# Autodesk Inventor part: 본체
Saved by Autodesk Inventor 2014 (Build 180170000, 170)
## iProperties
Created: 2025-02
Part Number: 본체
Material: 알루미늄 6061
Document SubType Name: Modeling
Designer: dg
Density: 2.71 g/cm^3
Appearance: 알루미늄 - 평지
Author: jhkim
Creation Date: 2025-01-06
Sending System: Autodesk Inventor 2025
Preprocessor: ST-DEVELOPER v20
Author: dg
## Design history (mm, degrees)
node "본체1"
node "솔리드1"
node "기준1"
